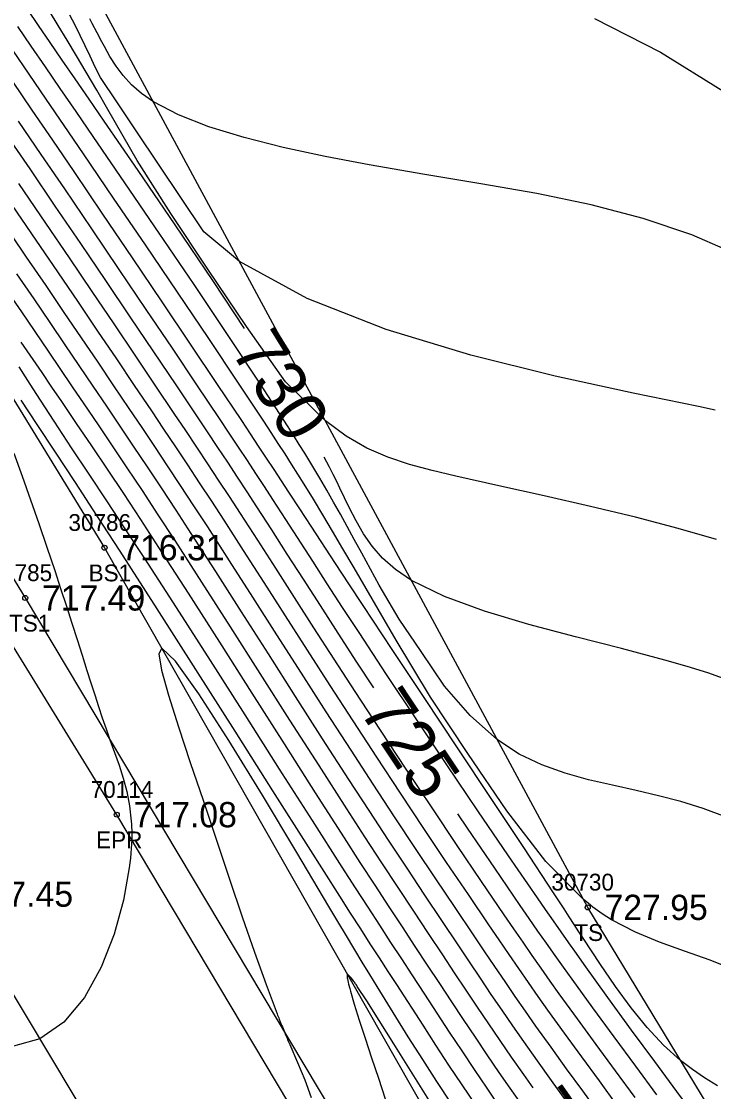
# Model space of a CAD drawing. Extents: x 1376587 to 1378239, y 1000335 to 1003031.
# Drawn here: x 1377155.3 to 1377196.4, y 1002003.4 to 1002067 of the extents above; entities that cross this region are included whole.
import ezdxf

# ---------------------------------------------------------------- set-up
doc = ezdxf.new("R2010")
doc.units = 0
for name, color, linetype in [('RD_DTM_BkLn1', 7, 'Continuous'), ('RD_DTM_BkLn2', 7, 'Continuous'), ('RD_DTM_BkLn_txCode', 7, 'Continuous'), ('RD_DTM_Major1', 7, 'Continuous'), ('RD_DTM_Major1_Lbl', 7, 'Continuous'), ('RD_DTM_Minor1', 7, 'Continuous'), ('RD_EX_Road', 7, 'Continuous'), ('RD_EX_Road_txCode', 7, 'Continuous'), ('RD_EX_TX_Misc_ELEV', 7, 'Continuous'), ('RD_EX_TX_Road_ELEV', 7, 'Continuous'), ('RD_HC_Survey_ELEV', 7, 'Continuous'), ('RD_SMD_Locator', 7, 'Continuous')]:
    doc.layers.add(name, color=color, linetype=linetype)

msp = doc.modelspace()

# ---------------------------------------------------------------- linework, layer by layer
at = {"layer": 'RD_DTM_BkLn1'}
msp.add_lwpolyline([(1377340.411, 1001702.156), (1377308.865, 1001753.727), (1377278.246, 1001805.238), (1377245.962, 1001858.008), (1377214.824, 1001910.42), (1377182.966, 1001962.109), (1377151.242, 1002015.115), (1377120.387, 1002065.538), (1377089.615, 1002116.564), (1377055.769, 1002172.475), (1377024.269, 1002225.826), (1377004.131, 1002257.876), (1377003.447, 1002259.314)], dxfattribs=at)
at = {"layer": 'RD_DTM_BkLn2'}
for points in [[(1377334.808, 1002026.055), (1377284.229, 1002013.339), (1377249.257, 1001988.727), (1377213.659, 1001973.589), (1377188.957, 1002014.33), (1377158.44, 1002070.963), (1377139.047, 1002104.941), (1377113.892, 1002149.475), (1377071.66, 1002218.399), (1377041.895, 1002260.076), (1377023.693, 1002288.088), (1377010.927, 1002302.495), (1376992.725, 1002332.02), (1376976.352, 1002351.559)], [(1376977.592, 1002343.743), (1376991.525, 1002318.779), (1377012.226, 1002283.102), (1377032.893, 1002247.364), (1377053.281, 1002213.6), (1377075.695, 1002176.413), (1377096.747, 1002142.056), (1377117.513, 1002106.979), (1377138.493, 1002071.226), (1377160.243, 1002035.712), (1377181.074, 1001999.107), (1377204.311, 1001959.476)], [(1376971.766, 1002339.684), (1376984.16, 1002314.581), (1377005.368, 1002280.112), (1377027.082, 1002243.848), (1377048.279, 1002210.776), (1377069.87, 1002173.423), (1377092.065, 1002138.92), (1377112.017, 1002104.252), (1377133.641, 1002068.495), (1377155.53, 1002032.726), (1377177.087, 1001996.618), (1377201.678, 1001958.67), (1377205.328, 1001957.618)]]:
    msp.add_lwpolyline(points, dxfattribs=at)
at = {"layer": 'RD_DTM_Major1'}
for points in [[(1377168.565, 1002048.755), (1377166.721, 1002051.544), (1377164.452, 1002054.912), (1377162.242, 1002058.151), (1377160.23, 1002061.079), (1377159.33, 1002062.386), (1377158.502, 1002063.588), (1377157.733, 1002064.705), (1377157.012, 1002065.756), (1377156.325, 1002066.761), (1377155.659, 1002067.741), (1377155.163, 1002068.476)], [(1377176.248, 1002027.39), (1377175.247, 1002028.917), (1377174.131, 1002030.635), (1377173.073, 1002032.274), (1377172.067, 1002033.84), (1377171.107, 1002035.338), (1377170.185, 1002036.772), (1377169.295, 1002038.148), (1377168.717, 1002039.036), (1377168.142, 1002039.913), (1377167.564, 1002040.791), (1377166.974, 1002041.681), (1377166.366, 1002042.596), (1377165.732, 1002043.547), (1377164.499, 1002045.39), (1377163.174, 1002047.365), (1377161.775, 1002049.444), (1377160.321, 1002051.6), (1377158.83, 1002053.803), (1377157.321, 1002056.026), (1377155.816, 1002058.238), (1377154.328, 1002060.42)], [(1377185.719, 1002003.605), (1377185.162, 1002004.391), (1377184.434, 1002005.431), (1377183.751, 1002006.421), (1377183.077, 1002007.409), (1377182.407, 1002008.405), (1377181.732, 1002009.414), (1377181.048, 1002010.443), (1377180.346, 1002011.5), (1377179.501, 1002012.774), (1377178.62, 1002014.104), (1377177.697, 1002015.501), (1377176.73, 1002016.973), (1377175.713, 1002018.531), (1377174.642, 1002020.183), (1377172.99, 1002022.755), (1377171.259, 1002025.468), (1377169.494, 1002028.243), (1377167.738, 1002031.001), (1377166.037, 1002033.662), (1377164.434, 1002036.148), (1377163.44, 1002037.675), (1377162.497, 1002039.107), (1377161.597, 1002040.463), (1377160.728, 1002041.762), (1377159.88, 1002043.023), (1377159.041, 1002044.264), (1377158.349, 1002045.286), (1377156.912, 1002047.401), (1377155.327, 1002049.73), (1377154.447, 1002051.019)], [(1377197.25, 1002027.86), (1377196.092, 1002028.269), (1377194.861, 1002028.657), (1377193.544, 1002029.035), (1377190.974, 1002029.712), (1377188.231, 1002030.41), (1377185.464, 1002031.147), (1377182.818, 1002031.941), (1377180.442, 1002032.809), (1377178.481, 1002033.77), (1377177.537, 1002034.412), (1377176.77, 1002035.091), (1377176.146, 1002035.804), (1377175.631, 1002036.547), (1377175.19, 1002037.317), (1377174.789, 1002038.109), (1377174.237, 1002039.248), (1377174.04, 1002039.649), (1377173.831, 1002040.066), (1377173.607, 1002040.502), (1377173.448, 1002040.804), (1377173.29, 1002041.097)], [(1377193.073, 1002003.186), (1377191.81, 1002004.896), (1377190.534, 1002006.623), (1377189.267, 1002008.348), (1377188.032, 1002010.051), (1377187.522, 1002010.764), (1377187.017, 1002011.475), (1377186.513, 1002012.192), (1377186.004, 1002012.92), (1377185.485, 1002013.667), (1377184.953, 1002014.438), (1377183.432, 1002016.655), (1377181.818, 1002019.033), (1377181.235, 1002019.898)], [(1377179.526, 1002002.884), (1377178.437, 1002004.625), (1377177.445, 1002006.216), (1377176.571, 1002007.611), (1377175.838, 1002008.764), (1377175.266, 1002009.632), (1377175.231, 1002009.684), (1377175.196, 1002009.734), (1377175.163, 1002009.782), (1377175.13, 1002009.829), (1377175.099, 1002009.873), (1377175.068, 1002009.916), (1377174.976, 1002010.041), (1377174.896, 1002010.144), (1377174.827, 1002010.225), (1377174.77, 1002010.283), (1377174.724, 1002010.316), (1377174.69, 1002010.324), (1377174.674, 1002010.314), (1377174.663, 1002010.291), (1377174.658, 1002010.256), (1377174.659, 1002010.207), (1377174.665, 1002010.147), (1377174.676, 1002010.075), (1377174.694, 1002009.985), (1377174.716, 1002009.882), (1377174.744, 1002009.767), (1377174.815, 1002009.502), (1377174.857, 1002009.352), (1377175.088, 1002008.576), (1377175.386, 1002007.631), (1377175.734, 1002006.557), (1377176.117, 1002005.392), (1377176.521, 1002004.175), (1377176.928, 1002002.947)]]:
    msp.add_lwpolyline(points, dxfattribs=at)
at = {"layer": 'RD_DTM_Minor1'}
for points in [[(1377196.61, 1002036.192), (1377194.338, 1002036.861), (1377191.805, 1002037.52), (1377189.115, 1002038.165), (1377186.369, 1002038.791), (1377183.671, 1002039.391), (1377181.124, 1002039.962), (1377179.71, 1002040.295), (1377178.368, 1002040.657), (1377177.081, 1002041.092), (1377175.831, 1002041.641), (1377174.601, 1002042.348), (1377173.371, 1002043.254), (1377171.008, 1002045.584), (1377168.678, 1002048.866), (1377166.388, 1002052.282), (1377164.181, 1002055.576), (1377162.187, 1002058.737), (1377160.449, 1002061.764), (1377159.78, 1002062.922), (1377159.16, 1002063.984), (1377158.58, 1002064.967), (1377158.028, 1002065.887), (1377157.496, 1002066.762), (1377156.972, 1002067.609)], [(1377196.528, 1002043.892), (1377195.534, 1002044.102), (1377191.651, 1002044.9), (1377187.028, 1002045.904), (1377182.021, 1002047.153), (1377176.986, 1002048.683), (1377172.281, 1002050.532), (1377168.261, 1002052.737), (1377166.15, 1002054.493), (1377163.457, 1002058.514), (1377162.162, 1002060.444), (1377160.967, 1002062.23), (1377160.002, 1002063.669), (1377159.69, 1002064.279), (1377159.391, 1002064.931), (1377159.097, 1002065.559), (1377158.803, 1002066.171), (1377158.503, 1002066.773), (1377158.192, 1002067.374)], [(1377197.139, 1002019.715), (1377195.818, 1002020.205), (1377194.497, 1002020.616), (1377193.173, 1002020.967), (1377191.843, 1002021.277), (1377190.428, 1002021.586), (1377189.013, 1002021.914), (1377187.61, 1002022.305), (1377186.231, 1002022.802), (1377184.888, 1002023.448), (1377183.591, 1002024.287), (1377181.966, 1002025.732), (1377180.446, 1002027.481), (1377179.052, 1002029.534), (1377177.746, 1002031.469), (1377176.574, 1002033.492), (1377175.527, 1002035.392), (1377175.087, 1002036.199), (1377174.666, 1002036.967), (1377174.258, 1002037.706), (1377173.855, 1002038.427), (1377173.449, 1002039.141), (1377173.033, 1002039.856), (1377172.747, 1002040.339), (1377172.45, 1002040.831), (1377172.142, 1002041.336), (1377171.819, 1002041.857), (1377171.479, 1002042.398), (1377171.121, 1002042.962), (1377169.481, 1002045.495), (1377167.598, 1002048.339), (1377165.569, 1002051.36), (1377163.491, 1002054.425), (1377161.461, 1002057.401), (1377159.575, 1002060.154), (1377158.557, 1002061.64), (1377157.611, 1002063.018), (1377156.727, 1002064.309), (1377155.893, 1002065.531), (1377155.095, 1002066.703)], [(1377197.148, 1002053.448), (1377195.14, 1002054.317), (1377192.253, 1002055.295), (1377189.164, 1002056.096), (1377185.932, 1002056.768), (1377182.616, 1002057.357), (1377179.277, 1002057.91), (1377175.975, 1002058.473), (1377173.362, 1002058.968), (1377170.867, 1002059.506), (1377168.544, 1002060.095), (1377166.448, 1002060.739), (1377164.632, 1002061.446), (1377163.151, 1002062.22), (1377162.441, 1002062.718), (1377161.85, 1002063.24), (1377161.355, 1002063.784), (1377160.935, 1002064.347), (1377160.569, 1002064.926), (1377160.234, 1002065.519), (1377160.093, 1002065.782), (1377159.81, 1002066.32), (1377159.517, 1002066.879), (1377159.364, 1002067.169)], [(1377189.363, 1002067.176), (1377193.277, 1002065.176), (1377196.997, 1002062.869), (1377200.551, 1002060.397), (1377203.965, 1002057.901), (1377207.267, 1002055.525), (1377210.485, 1002053.409), (1377212.861, 1002052.065), (1377215.235, 1002050.918), (1377217.634, 1002049.938), (1377220.088, 1002049.096), (1377222.627, 1002048.362), (1377225.279, 1002047.707)], [(1377197.796, 1002010.559), (1377196.231, 1002011.183), (1377194.71, 1002011.724), (1377193.23, 1002012.256), (1377191.789, 1002012.855), (1377190.382, 1002013.595), (1377190.103, 1002013.768), (1377189.824, 1002013.95), (1377189.545, 1002014.144), (1377189.266, 1002014.35), (1377188.985, 1002014.57), (1377188.701, 1002014.804), (1377186.467, 1002017.063), (1377184.15, 1002020.069), (1377181.838, 1002023.482), (1377179.625, 1002026.818), (1377177.578, 1002030.225), (1377175.788, 1002033.29), (1377175.07, 1002034.524), (1377174.411, 1002035.651), (1377173.799, 1002036.692), (1377173.22, 1002037.666), (1377172.661, 1002038.593), (1377172.109, 1002039.491), (1377171.739, 1002040.084), (1377171.363, 1002040.681), (1377170.975, 1002041.288), (1377170.572, 1002041.912), (1377170.15, 1002042.562), (1377169.703, 1002043.243), (1377168.166, 1002045.565), (1377166.434, 1002048.155), (1377164.579, 1002050.91), (1377162.673, 1002053.726), (1377160.787, 1002056.501), (1377158.994, 1002059.132), (1377157.849, 1002060.81), (1377156.773, 1002062.385), (1377155.757, 1002063.874), (1377154.792, 1002065.289)], [(1377196.666, 1002003.724), (1377195.905, 1002004.2), (1377195.177, 1002004.693), (1377194.479, 1002005.223), (1377193.457, 1002006.144), (1377192.484, 1002007.191), (1377191.542, 1002008.354), (1377190.613, 1002009.622), (1377189.68, 1002010.985), (1377188.726, 1002012.433), (1377188.44, 1002012.872), (1377188.15, 1002013.317), (1377187.855, 1002013.771), (1377187.554, 1002014.235), (1377186.93, 1002015.193), (1377185.158, 1002017.889), (1377183.231, 1002020.8), (1377181.23, 1002023.808), (1377179.239, 1002026.8), (1377177.338, 1002029.658), (1377175.611, 1002032.269), (1377174.756, 1002033.572), (1377173.966, 1002034.781), (1377172.531, 1002036.986), (1377171.86, 1002038.017), (1377171.203, 1002039.023), (1377170.767, 1002039.689), (1377170.325, 1002040.36), (1377169.873, 1002041.045), (1377169.404, 1002041.753), (1377168.914, 1002042.492), (1377168.395, 1002043.271), (1377166.957, 1002045.425), (1377165.362, 1002047.808), (1377163.66, 1002050.342), (1377161.904, 1002052.95), (1377160.146, 1002055.554), (1377158.437, 1002058.076), (1377157.164, 1002059.95), (1377155.951, 1002061.734), (1377154.794, 1002063.433)], [(1377195.438, 1002001.771), (1377194.245, 1002003.387), (1377192.941, 1002005.157), (1377191.564, 1002007.035), (1377190.152, 1002008.977), (1377188.744, 1002010.938), (1377188.287, 1002011.582), (1377187.832, 1002012.227), (1377187.375, 1002012.877), (1377186.916, 1002013.534), (1377186.45, 1002014.203), (1377185.975, 1002014.888), (1377184.247, 1002017.401), (1377182.433, 1002020.066), (1377180.586, 1002022.803), (1377178.758, 1002025.534), (1377177.001, 1002028.181), (1377175.368, 1002030.666), (1377174.391, 1002032.165), (1377173.479, 1002033.575), (1377172.619, 1002034.908), (1377171.018, 1002037.394), (1377170.254, 1002038.574), (1377169.751, 1002039.346), (1377169.245, 1002040.117), (1377168.732, 1002040.897), (1377168.202, 1002041.697), (1377167.651, 1002042.527), (1377167.072, 1002043.398), (1377165.736, 1002045.399), (1377164.276, 1002047.577), (1377162.727, 1002049.882), (1377161.122, 1002052.263), (1377159.495, 1002054.669), (1377157.881, 1002057.049), (1377156.488, 1002059.098), (1377155.137, 1002061.081)], [(1377191.774, 1002003.031), (1377190.61, 1002004.612), (1377189.464, 1002006.167), (1377188.347, 1002007.695), (1377187.268, 1002009.19), (1377186.728, 1002009.949), (1377186.194, 1002010.707), (1377185.661, 1002011.472), (1377185.121, 1002012.252), (1377184.569, 1002013.056), (1377183.997, 1002013.891), (1377182.65, 1002015.87), (1377181.21, 1002018.001), (1377179.708, 1002020.239), (1377178.174, 1002022.541), (1377176.639, 1002024.863), (1377175.135, 1002027.16), (1377173.888, 1002029.084), (1377172.686, 1002030.951), (1377171.529, 1002032.756), (1377170.417, 1002034.493), (1377169.349, 1002036.156), (1377168.327, 1002037.74), (1377167.669, 1002038.75), (1377167.023, 1002039.735), (1377166.38, 1002040.709), (1377165.733, 1002041.686), (1377165.072, 1002042.677), (1377164.39, 1002043.698), (1377163.263, 1002045.379), (1377162.07, 1002047.155), (1377160.817, 1002049.015), (1377159.51, 1002050.95), (1377158.155, 1002052.951), (1377156.759, 1002055.006), (1377155.147, 1002057.372)], [(1377190.718, 1002002.552), (1377189.651, 1002004.009), (1377188.603, 1002005.439), (1377187.581, 1002006.842), (1377186.594, 1002008.214), (1377186.011, 1002009.037), (1377185.436, 1002009.858), (1377184.863, 1002010.685), (1377184.284, 1002011.528), (1377183.691, 1002012.397), (1377183.078, 1002013.3), (1377181.866, 1002015.09), (1377180.576, 1002017.006), (1377179.227, 1002019.022), (1377177.837, 1002021.113), (1377176.426, 1002023.253), (1377175.012, 1002025.416), (1377173.647, 1002027.525), (1377172.307, 1002029.613), (1377170.998, 1002031.658), (1377169.731, 1002033.642), (1377168.513, 1002035.543), (1377167.352, 1002037.342), (1377166.613, 1002038.477), (1377165.894, 1002039.573), (1377165.187, 1002040.643), (1377164.483, 1002041.702), (1377163.773, 1002042.765), (1377163.049, 1002043.846), (1377162.03, 1002045.364), (1377160.966, 1002046.945), (1377159.853, 1002048.595), (1377158.688, 1002050.316), (1377157.468, 1002052.115), (1377156.191, 1002053.993), (1377154.48, 1002056.505)], [(1377189.637, 1002002.073), (1377188.662, 1002003.417), (1377187.708, 1002004.729), (1377186.781, 1002006.013), (1377185.884, 1002007.271), (1377185.266, 1002008.152), (1377184.656, 1002009.031), (1377184.049, 1002009.916), (1377183.437, 1002010.817), (1377182.811, 1002011.742), (1377182.164, 1002012.703), (1377181.08, 1002014.314), (1377179.933, 1002016.026), (1377178.732, 1002017.827), (1377177.485, 1002019.709), (1377176.202, 1002021.659), (1377174.892, 1002023.668), (1377173.42, 1002025.948), (1377171.944, 1002028.251), (1377170.483, 1002030.54), (1377169.056, 1002032.777), (1377167.68, 1002034.925), (1377166.376, 1002036.948), (1377165.552, 1002038.212), (1377164.76, 1002039.419), (1377163.988, 1002040.585), (1377163.229, 1002041.726), (1377162.473, 1002042.855), (1377161.71, 1002043.99), (1377160.8, 1002045.342), (1377159.86, 1002046.736), (1377158.881, 1002048.184), (1377157.854, 1002049.701), (1377156.769, 1002051.299), (1377155.617, 1002052.992), (1377153.811, 1002055.64)], [(1377187.672, 1002002.833), (1377186.81, 1002004.031), (1377185.974, 1002005.2), (1377185.163, 1002006.348), (1377184.511, 1002007.283), (1377183.869, 1002008.217), (1377183.23, 1002009.157), (1377182.586, 1002010.113), (1377181.93, 1002011.091), (1377181.254, 1002012.102), (1377180.292, 1002013.542), (1377179.281, 1002015.059), (1377178.222, 1002016.654), (1377177.116, 1002018.328), (1377175.965, 1002020.084), (1377174.769, 1002021.923), (1377173.202, 1002024.357), (1377171.596, 1002026.868), (1377169.982, 1002029.401), (1377168.391, 1002031.897), (1377166.854, 1002034.3), (1377165.401, 1002036.553), (1377164.493, 1002037.948), (1377163.625, 1002039.267), (1377162.789, 1002040.529), (1377161.975, 1002041.748), (1377161.174, 1002042.943), (1377160.375, 1002044.129), (1377159.574, 1002045.316), (1377157.902, 1002047.786), (1377157.006, 1002049.105), (1377156.054, 1002050.505), (1377155.034, 1002052.002)], [(1377185.017, 1002002.627), (1377184.352, 1002003.577), (1377183.703, 1002004.513), (1377182.989, 1002005.557), (1377182.283, 1002006.603), (1377181.581, 1002007.655), (1377180.877, 1002008.718), (1377180.164, 1002009.798), (1377179.438, 1002010.901), (1377178.707, 1002012.012), (1377177.949, 1002013.164), (1377177.158, 1002014.37), (1377176.326, 1002015.645), (1377175.444, 1002017.002), (1377174.507, 1002018.454), (1377172.782, 1002021.148), (1377170.932, 1002024.055), (1377169.018, 1002027.069), (1377167.098, 1002030.089), (1377165.231, 1002033.011), (1377163.479, 1002035.73), (1377162.398, 1002037.386), (1377161.382, 1002038.93), (1377160.416, 1002040.381), (1377159.49, 1002041.764), (1377158.588, 1002043.099), (1377157.699, 1002044.408), (1377157.121, 1002045.259), (1377156.532, 1002046.122), (1377155.29, 1002047.941)], [(1377183.548, 1002002.751), (1377182.978, 1002003.582), (1377182.229, 1002004.69), (1377181.489, 1002005.798), (1377180.753, 1002006.91), (1377180.016, 1002008.032), (1377179.274, 1002009.167), (1377178.522, 1002010.319), (1377177.903, 1002011.268), (1377177.266, 1002012.245), (1377176.603, 1002013.264), (1377175.905, 1002014.339), (1377175.165, 1002015.484), (1377174.374, 1002016.713), (1377172.595, 1002019.494), (1377170.647, 1002022.554), (1377168.602, 1002025.767), (1377166.535, 1002029.008), (1377164.519, 1002032.15), (1377162.63, 1002035.067), (1377161.47, 1002036.837), (1377160.375, 1002038.495), (1377159.323, 1002040.084), (1377158.291, 1002041.649), (1377157.254, 1002043.232), (1377156.191, 1002044.877), (1377155.69, 1002045.66), (1377155.175, 1002046.472)], [(1377182.282, 1002002.6), (1377181.492, 1002003.781), (1377180.714, 1002004.956), (1377179.942, 1002006.133), (1377179.171, 1002007.317), (1377177.606, 1002009.736), (1377177.1, 1002010.52), (1377176.58, 1002011.326), (1377176.039, 1002012.166), (1377175.471, 1002013.05), (1377174.869, 1002013.99), (1377174.226, 1002014.996), (1377172.358, 1002017.933), (1377170.254, 1002021.251), (1377167.999, 1002024.809), (1377165.677, 1002028.466), (1377163.372, 1002032.081), (1377161.168, 1002035.513), (1377159.795, 1002037.633), (1377158.512, 1002039.6), (1377157.327, 1002041.403), (1377156.249, 1002043.034), (1377155.285, 1002044.483)], [(1377154.862, 1002041.334), (1377155.348, 1002039.966), (1377155.842, 1002038.563), (1377156.334, 1002037.146), (1377156.817, 1002035.737), (1377157.282, 1002034.357), (1377157.637, 1002033.284), (1377157.977, 1002032.243), (1377158.302, 1002031.235), (1377158.614, 1002030.261), (1377158.914, 1002029.32), (1377159.202, 1002028.412), (1377159.435, 1002027.677), (1377159.663, 1002026.964), (1377159.889, 1002026.27), (1377160.113, 1002025.595), (1377160.338, 1002024.935), (1377160.567, 1002024.289), (1377160.842, 1002023.537), (1377161.111, 1002022.785), (1377161.359, 1002022.016), (1377161.572, 1002021.216), (1377161.736, 1002020.367), (1377161.837, 1002019.453), (1377161.848, 1002019.278), (1377161.856, 1002019.1), (1377161.861, 1002018.919), (1377161.863, 1002018.735), (1377161.863, 1002018.547), (1377161.859, 1002018.355), (1377161.849, 1002018.093), (1377161.834, 1002017.824), (1377161.813, 1002017.547), (1377161.787, 1002017.264), (1377161.755, 1002016.973), (1377161.717, 1002016.676), (1377161.369, 1002014.759), (1377160.81, 1002012.741), (1377160.037, 1002010.765), (1377159.045, 1002008.973), (1377157.832, 1002007.506), (1377156.393, 1002006.508), (1377154.842, 1002006.086)], [(1377180.836, 1002002.692), (1377179.996, 1002003.972), (1377179.153, 1002005.279), (1377178.29, 1002006.639), (1377177.39, 1002008.08), (1377176.439, 1002009.628), (1377176.01, 1002010.334), (1377175.565, 1002011.068), (1377174.619, 1002012.642), (1377174.112, 1002013.49), (1377173.579, 1002014.384), (1377171.671, 1002017.592), (1377169.631, 1002020.996), (1377167.634, 1002024.254), (1377165.854, 1002027.024), (1377164.466, 1002028.965), (1377163.645, 1002029.734), (1377163.481, 1002029.412), (1377163.636, 1002028.435), (1377164.042, 1002026.94), (1377164.633, 1002025.061), (1377165.341, 1002022.936), (1377166.098, 1002020.699), (1377166.899, 1002018.317), (1377167.675, 1002015.997), (1377168.426, 1002013.771), (1377169.149, 1002011.673), (1377169.841, 1002009.736), (1377170.499, 1002007.994), (1377170.531, 1002007.913), (1377170.563, 1002007.832), (1377170.595, 1002007.752), (1377170.627, 1002007.673), (1377170.69, 1002007.515), (1377170.731, 1002007.415), (1377170.771, 1002007.317), (1377170.811, 1002007.219), (1377170.891, 1002007.025), (1377170.931, 1002006.929), (1377170.985, 1002006.801), (1377171.039, 1002006.674), (1377171.093, 1002006.548), (1377171.147, 1002006.423), (1377171.2, 1002006.3), (1377171.254, 1002006.177), (1377171.722, 1002005.109), (1377172.154, 1002004.073), (1377172.528, 1002003.034)]]:
    msp.add_lwpolyline(points, dxfattribs=at)
at = {"layer": 'RD_EX_Road'}
msp.add_lwpolyline([(1377350.339, 1001708.261), (1377317.923, 1001758.892), (1377286.961, 1001809.893), (1377254.767, 1001863.401), (1377224.604, 1001914.857), (1377192.26, 1001967.361), (1377160.973, 1002019.841), (1377129.715, 1002070.663), (1377099.389, 1002121.709), (1377064.159, 1002179.082), (1377033.485, 1002231.09), (1377014.7, 1002262.97), (1377013.314, 1002264.907)], dxfattribs=at)
at = {"layer": 'RD_SMD_Locator'}
for centre in [(1377160.243, 1002035.712), (1377155.53, 1002032.726), (1377160.973, 1002019.841), (1377188.957, 1002014.33)]:
    msp.add_circle(centre, 0.15, dxfattribs=at)

# ---------------------------------------------------------------- texts
at = {"layer": 'RD_DTM_BkLn_txCode'}
for s, p in [('30786', (1377158.101, 1002036.712)), ('30785', (1377153.412, 1002033.726)), ('BS1', (1377159.298, 1002033.712)), ('TS1', (1377154.569, 1002030.726)), ('30730', (1377186.8, 1002015.33)), ('TS', (1377188.162, 1002012.33))]:
    msp.add_text(s, height=1, dxfattribs=at).set_placement(p)
at = {"layer": 'RD_DTM_Major1_Lbl'}
for s, rotation, p in [('730', 301.67519, (1377167.698, 1002047.458)), ('725', 303.65006, (1377175.321, 1002026.05)), ('720', 305.02853, (1377184.857, 1002002.265))]:
    msp.add_text(s, height=3, rotation=rotation, dxfattribs=at).set_placement(p)
at = {"layer": 'RD_EX_Road_txCode'}
for s, p in [('70114', (1377159.422, 1002020.841)), ('EPR', (1377159.745, 1002017.841))]:
    msp.add_text(s, height=1, dxfattribs=at).set_placement(p)
at = {"layer": 'RD_EX_TX_Misc_ELEV'}
for s, p in [('716.31', (1377161.243, 1002034.962)), ('717.49', (1377156.53, 1002031.976)), ('727.95', (1377189.957, 1002013.58))]:
    msp.add_text(s, height=1.5, dxfattribs=at).set_placement(p)
at = {"layer": 'RD_EX_TX_Road_ELEV'}
msp.add_text('717.08', height=1.5, dxfattribs=at).set_placement((1377161.973, 1002019.091))
at = {"layer": 'RD_HC_Survey_ELEV'}
msp.add_text('717.45', height=1.5, dxfattribs=at).set_placement((1377152.242, 1002014.365))

doc.saveas('drawing.dxf')
